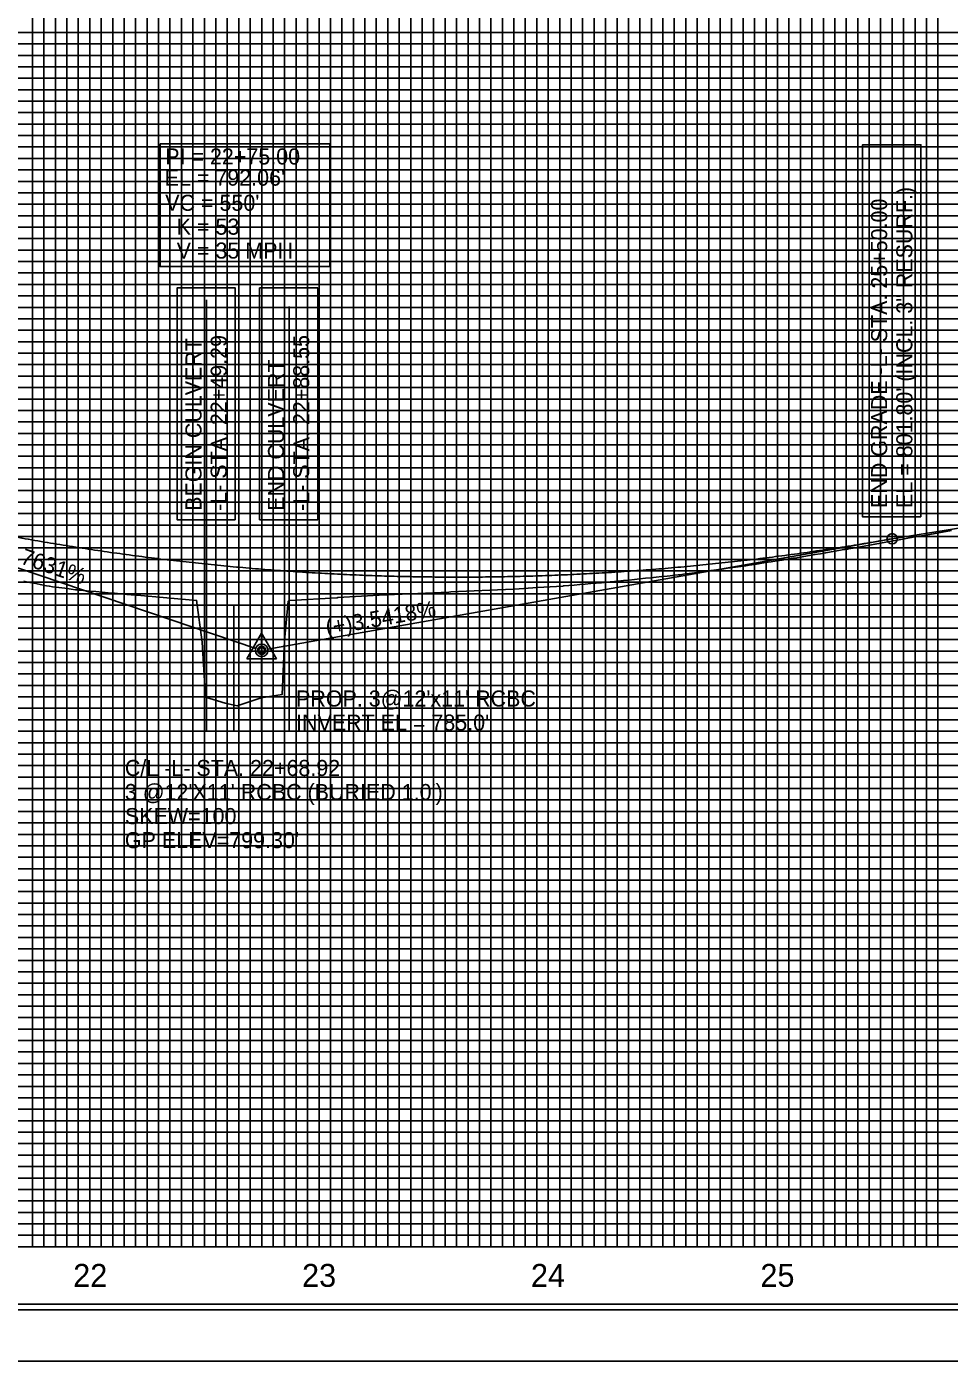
# Model space of a CAD drawing. Extents: x 573566 to 575250, y -53414 to -52314.
# Drawn here: x 574256 to 574658, y -53414 to -52832 of the extents above; entities that cross this region are included whole.
import ezdxf

# ---------------------------------------------------------------- set-up
doc = ezdxf.new("R2010")
doc.units = 0
for name, color, linetype in [('Default', 7, 'Continuous'), ('Exist Vertical Profile Ground Line', 7, 'Continuous'), ('Exist Vertical Profile Horizontal Axis Label Major', 7, 'Continuous'), ('Prop Grid Mask', 7, 'Continuous'), ('Prop PFL VPI Symbol CELL', 7, 'Continuous'), ('Prop Roadway Culvert', 7, 'Continuous'), ('Prop Vertical Profile Curve Label', 7, 'Continuous'), ('Prop Vertical Profile Grade', 7, 'Continuous'), ('Prop Vertical Profile Grade Label', 7, 'Continuous'), ('Prop VPI Label', 7, 'Continuous'), ('Sheet Cutting Line CELL', 7, 'Continuous'), ('Sheet DOT Grid CELL', 7, 'Continuous'), ('Sheet Layout Profile Border', 7, 'Continuous'), ('Sheet Plot Border Inside CELL', 7, 'Continuous'), ('Sheet Plot Border Outside CELL', 7, 'Continuous'), ('Sheet Profile CELL', 7, 'Continuous'), ('Sheet Profile Grid Major CELL', 7, 'Continuous'), ('Sheet Profile Grid Middle CELL', 7, 'Continuous'), ('Sheet Profile Grid Minor CELL', 7, 'Continuous')]:
    doc.layers.add(name, color=color, linetype=linetype)

msp = doc.modelspace()

# ---------------------------------------------------------------- linework, layer by layer
at = {"layer": 'Default'}
for p, q in [((574370.23, -53084.05), (574334.23, -53084.05)), ((574358.23, -53084.05), (574358.23, -53139.05))]:
    msp.add_line(p, q, dxfattribs=at)
at = {"layer": 'Exist Vertical Profile Ground Line'}
for points in [[(574606.77, -53060.75), (574609.15, -53060.34), (574611.54, -53059.93), (574612.73, -53059.73), (574613.92, -53059.53), (574614.33, -53059.46), (574616.31, -53059.11), (574618.69, -53058.68), (574621.08, -53058.25), (574623.47, -53057.82), (574625.85, -53057.39), (574628.24, -53056.96), (574630.62, -53056.53), (574633.01, -53056.11), (574635.39, -53055.68), (574636.4, -53055.5), (574637.78, -53055.27), (574638.68, -53055.12), (574640.16, -53054.85), (574642.55, -53054.41), (574644.93, -53053.98), (574647.32, -53053.55), (574649.7, -53053.12), (574652.09, -53052.68), (574654.47, -53052.25), (574656.86, -53051.82), (574659.25, -53051.39)], [(574261.72, -53075), (574264.42, -53075.53), (574265.72, -53075.79), (574267.12, -53075.97), (574269.81, -53076.32), (574272.51, -53076.67), (574275.21, -53077.02), (574277.12, -53077.27), (574277.9, -53077.38), (574278.31, -53077.44), (574280.6, -53077.65), (574283.3, -53077.89), (574285.99, -53078.13), (574288.69, -53078.38), (574291.39, -53078.61), (574294.08, -53078.85), (574296.78, -53079.09), (574299.48, -53079.32), (574303.21, -53079.65), (574304.04, -53079.7), (574329.89, -53081.96), (574329.92, -53081.9), (574332.41, -53100.16), (574333.76, -53124.19), (574342.33, -53126.75), (574347.68, -53128.02), (574354.21, -53125.83), (574358.02, -53124.4), (574367.22, -53123.06), (574368.19, -53099.62), (574369.93, -53082.34), (574370.37, -53081.94), (574391.18, -53080.77), (574391.57, -53080.75), (574412.16, -53079.59), (574412.93, -53079.55), (574439.93, -53078.3), (574440.86, -53078.25), (574467.94, -53077.07), (574468.66, -53077.03), (574478.69, -53076.38), (574489.68, -53075.67), (574489.89, -53075.65), (574490.3, -53075.62), (574492.27, -53075.45), (574494.66, -53075.24), (574497.04, -53075.04), (574499.43, -53074.83), (574501.82, -53074.62), (574504.2, -53074.42), (574506.59, -53074.21), (574508.97, -53074), (574510.26, -53073.89), (574511.36, -53073.8), (574512.18, -53073.74), (574513.74, -53073.57), (574516.13, -53073.32), (574518.51, -53073.07), (574520.9, -53072.82), (574523.28, -53072.57), (574525.67, -53072.31), (574528.05, -53072.06), (574530.44, -53071.81), (574532.82, -53071.56), (574535.21, -53071.31), (574537.59, -53071.05), (574538.1, -53071), (574539.98, -53070.81), (574540.84, -53070.73), (574542.37, -53070.52), (574544.75, -53070.2), (574547.14, -53069.88), (574549.52, -53069.56), (574551.91, -53069.23), (574554.29, -53068.91), (574556.68, -53068.59), (574559.06, -53068.26), (574561.45, -53067.94), (574563.83, -53067.61), (574566.22, -53067.29), (574568.6, -53066.96), (574568.61, -53066.96), (574569.46, -53066.84), (574570.99, -53066.6), (574573.37, -53066.23), (574575.76, -53065.85), (574578.14, -53065.47), (574580.53, -53065.09), (574582.92, -53064.71), (574582.99, -53064.7), (574585.3, -53064.34), (574587.69, -53063.96), (574590.07, -53063.58), (574591.81, -53063.31), (574592.46, -53063.2), (574594.84, -53062.79), (574597.23, -53062.38), (574599.61, -53061.98), (574602, -53061.57), (574604.38, -53061.16), (574606.77, -53060.75)], [(574254.52, -53073.59), (574256.33, -53073.95), (574259.03, -53074.48), (574261.72, -53075)]]:
    msp.add_lwpolyline(points, dxfattribs=at)
at = {"layer": 'Prop Grid Mask'}
for points in [[(574314.01, -52882.62), (574388.03, -52882.62), (574388.03, -52936.22), (574314.01, -52936.22)], [(574645.87, -53045.49), (574620.46, -53045.49), (574620.46, -52883.04), (574645.87, -52883.04)], [(574346.79, -53046.76), (574321.38, -53046.76), (574321.38, -52945.55), (574346.79, -52945.55)], [(574382.79, -53046.76), (574357.38, -53046.76), (574357.38, -52945.55), (574382.79, -52945.55)]]:
    msp.add_lwpolyline(points, close=True, dxfattribs=at)
at = {"layer": 'Prop PFL VPI Symbol CELL'}
for p, q in [((574358.3, -53096.27), (574351.85, -53107.47)), ((574358.3, -53096.27), (574364.8, -53107.47)), ((574351.85, -53107.47), (574364.8, -53107.47))]:
    msp.add_line(p, q, dxfattribs=at)
for radius in [1.75, 1.2]:
    msp.add_circle((574358.31, -53103.75), radius, dxfattribs=at)
at = {"layer": 'Prop Roadway Culvert'}
for p, q in [((574334.23, -53079.05), (574370.23, -53079.05)), ((574334.23, -53139.05), (574334.23, -53079.05)), ((574370.23, -53139.05), (574370.23, -53079.05)), ((574334.23, -53084.05), (574370.23, -53084.05)), ((574346.23, -53139.05), (574346.23, -53084.05)), ((574358.23, -53139.05), (574358.23, -53084.05)), ((574334.23, -53139.05), (574370.23, -53139.05))]:
    msp.add_line(p, q, dxfattribs=at)
at = {"layer": 'Prop Vertical Profile Curve Label'}
msp.add_circle((574633.31, -53055.05), 2.25, dxfattribs=at)
at = {"layer": 'Prop Vertical Profile Grade'}
msp.add_line((574633.31, -53055.05), (574683.31, -53047.03), dxfattribs=at)
msp.add_spline([(574083.31, -53010.76), (574094.31, -53014.42), (574105.31, -53017.97), (574116.31, -53021.41), (574127.31, -53024.73), (574138.31, -53027.94), (574149.31, -53031.03), (574160.31, -53034.02), (574171.31, -53036.89), (574182.31, -53039.64), (574193.31, -53042.29), (574204.31, -53044.82), (574215.31, -53047.23), (574226.31, -53049.53), (574237.31, -53051.72), (574248.31, -53053.8), (574259.31, -53055.76), (574270.31, -53057.61), (574281.31, -53059.35), (574292.31, -53060.97), (574303.31, -53062.48), (574314.31, -53063.88), (574325.31, -53065.16), (574336.31, -53066.33), (574347.31, -53067.38), (574358.31, -53068.33), (574369.31, -53069.16), (574380.31, -53069.87), (574391.31, -53070.47), (574402.31, -53070.96), (574413.31, -53071.34), (574424.31, -53071.6), (574435.31, -53071.75), (574446.31, -53071.79), (574457.31, -53071.71), (574468.31, -53071.52), (574479.31, -53071.21), (574490.31, -53070.79), (574501.31, -53070.26), (574512.31, -53069.62), (574523.31, -53068.86), (574534.31, -53067.99), (574545.31, -53067.01), (574556.31, -53065.91), (574567.31, -53064.7), (574578.31, -53063.37), (574589.31, -53061.93), (574600.31, -53060.38), (574611.31, -53058.72), (574622.31, -53056.94), (574633.31, -53055.05)], degree=3, dxfattribs=at)
at = {"layer": 'Prop VPI Label'}
for p, q in [((574633.31, -53055.05), (574633.31, -52884.81)), ((574334.23, -53079.05), (574334.23, -52950.82)), ((574370.23, -53079.05), (574370.23, -52953.7)), ((574083.31, -53010.76), (574355.7, -53102.87)), ((574633.31, -53055.05), (574361.01, -53103.27))]:
    msp.add_line(p, q, dxfattribs=at)
msp.add_circle((574358.31, -53103.75), 2.75, dxfattribs=at)
at = {"layer": 'Sheet Cutting Line CELL'}
msp.add_line((573566.31, -53414.05), (575250.31, -53414.05), dxfattribs=at)
at = {"layer": 'Sheet DOT Grid CELL'}
for p, q in [((574283.31, -52339.05), (574283.31, -53364.05)), ((574333.31, -52339.05), (574333.31, -53364.05)), ((574383.31, -52339.05), (574383.31, -53364.05)), ((574433.31, -52339.05), (574433.31, -53364.05)), ((574483.31, -52339.05), (574483.31, -53364.05)), ((574533.31, -52339.05), (574533.31, -53364.05)), ((574583.31, -52339.05), (574583.31, -53364.05)), ((574633.31, -52339.05), (574633.31, -53364.05)), ((573733.31, -52864.05), (575233.31, -52864.05)), ((573733.31, -52914.05), (575233.31, -52914.05)), ((573733.31, -52964.05), (575233.31, -52964.05)), ((573733.31, -53014.05), (575233.31, -53014.05)), ((573733.31, -53064.05), (575233.31, -53064.05)), ((573733.31, -53114.05), (575233.31, -53114.05)), ((573733.31, -53164.05), (575233.31, -53164.05)), ((573733.31, -53214.05), (575233.31, -53214.05)), ((573733.31, -53264.05), (575233.31, -53264.05)), ((573733.31, -53314.05), (575233.31, -53314.05))]:
    msp.add_line(p, q, dxfattribs=at)
at = {"layer": 'Sheet Layout Profile Border'}
msp.add_lwpolyline([(573783.31, -52339.05), (573783.31, -53364.05), (575183.31, -53364.05), (575183.31, -52476.6), (575033.26, -52476.6), (575033.26, -52339.05)], close=True, dxfattribs=at)
at = {"layer": 'Sheet Plot Border Inside CELL'}
msp.add_lwpolyline([(575245.81, -52336.5), (573579.31, -52336.5), (573579.31, -53391.6), (575245.81, -53391.6)], close=True, dxfattribs=at)
at = {"layer": 'Sheet Plot Border Outside CELL'}
msp.add_lwpolyline([(575250.31, -52314.05), (573566.31, -52314.05), (573566.31, -53414.05), (575250.31, -53414.05)], close=True, dxfattribs=at)
at = {"layer": 'Sheet Profile CELL'}
msp.add_line((575233.31, -53364.05), (573733.31, -53364.05), dxfattribs=at)
msp.add_lwpolyline([(575233.31, -52339.05), (573733.31, -52339.05), (573733.31, -53389.05), (575233.31, -53389.05)], close=True, dxfattribs=at)
at = {"layer": 'Sheet Profile Grid Major CELL'}
for points in [[(574283.31, -52339.05), (574283.31, -53364.05), (574333.31, -53364.05), (574333.31, -52339.05)], [(574383.31, -52339.05), (574383.31, -53364.05), (574433.31, -53364.05), (574433.31, -52339.05)], [(574483.31, -52339.05), (574483.31, -53364.05), (574533.31, -53364.05), (574533.31, -52339.05)], [(574583.31, -52339.05), (574583.31, -53364.05), (574633.31, -53364.05), (574633.31, -52339.05)], [(575233.31, -52914.05), (573733.31, -52914.05), (573733.31, -52864.05), (575233.31, -52864.05)], [(575233.31, -53014.05), (573733.31, -53014.05), (573733.31, -52964.05), (575233.31, -52964.05)], [(575233.31, -53114.05), (573733.31, -53114.05), (573733.31, -53064.05), (575233.31, -53064.05)], [(575233.31, -53214.05), (573733.31, -53214.05), (573733.31, -53164.05), (575233.31, -53164.05)], [(575233.31, -53314.05), (573733.31, -53314.05), (573733.31, -53264.05), (575233.31, -53264.05)]]:
    msp.add_lwpolyline(points, dxfattribs=at)
at = {"layer": 'Sheet Profile Grid Middle CELL'}
for points in [[(574258.31, -52339.05), (574258.31, -53364.05), (574308.31, -53364.05), (574308.31, -52339.05)], [(574358.31, -52339.05), (574358.31, -53364.05), (574408.31, -53364.05), (574408.31, -52339.05)], [(574458.31, -52339.05), (574458.31, -53364.05), (574508.31, -53364.05), (574508.31, -52339.05)], [(574558.31, -52339.05), (574558.31, -53364.05), (574608.31, -53364.05), (574608.31, -52339.05)], [(575233.31, -52839.05), (573733.31, -52839.05), (573733.31, -52889.05), (575233.31, -52889.05)], [(575233.31, -52939.05), (573733.31, -52939.05), (573733.31, -52989.05), (575233.31, -52989.05)], [(575233.31, -53039.05), (573733.31, -53039.05), (573733.31, -53089.05), (575233.31, -53089.05)], [(575233.31, -53139.05), (573733.31, -53139.05), (573733.31, -53189.05), (575233.31, -53189.05)], [(575233.31, -53239.05), (573733.31, -53239.05), (573733.31, -53289.05), (575233.31, -53289.05)], [(575233.31, -53339.05), (573733.31, -53339.05)]]:
    msp.add_lwpolyline(points, dxfattribs=at)
at = {"layer": 'Sheet Profile Grid Minor CELL'}
for points in [[(574263.31, -52339.05), (574263.31, -53364.05)], [(574268.31, -52339.05), (574268.31, -53364.05), (574273.31, -53364.05), (574273.31, -52339.05), (574278.31, -52339.05), (574278.31, -53364.05), (574288.31, -53364.05), (574288.31, -52339.05), (574293.31, -52339.05), (574293.31, -53364.05), (574298.31, -53364.05), (574298.31, -52339.05), (574303.31, -52339.05), (574303.31, -53364.05)], [(574313.31, -53364.05), (574313.31, -52339.05)], [(574318.31, -52339.05), (574318.31, -53364.05), (574323.31, -53364.05), (574323.31, -52339.05)], [(574328.31, -52339.05), (574328.31, -53364.05), (574338.31, -53364.05), (574338.31, -52339.05)], [(574343.31, -52339.05), (574343.31, -53364.05), (574343.31, -53364.05), (574348.31, -53364.05), (574348.31, -52339.05)], [(574353.31, -52339.05), (574353.31, -53364.05), (574363.31, -53364.05), (574363.31, -52339.05)], [(574368.31, -52339.05), (574368.31, -53364.05), (574373.31, -53364.05), (574373.31, -52339.05)], [(574378.31, -52339.05), (574378.31, -53364.05), (574388.31, -53364.05), (574388.31, -52339.05)], [(574393.31, -52339.05), (574393.31, -53364.05), (574398.31, -53364.05), (574398.31, -52339.05)], [(574403.31, -52339.05), (574403.31, -53364.05), (574413.31, -53364.05), (574413.31, -52339.05)], [(574418.31, -52339.05), (574418.31, -53364.05), (574423.31, -53364.05), (574423.31, -52339.05)], [(574428.31, -52339.05), (574428.31, -53364.05), (574438.31, -53364.05), (574438.31, -52339.05)], [(574443.31, -52339.05), (574443.31, -53364.05), (574448.31, -53364.05), (574448.31, -52339.05)], [(574453.31, -52339.05), (574453.31, -53364.05), (574463.31, -53364.05), (574463.31, -52339.05)], [(574468.31, -52339.05), (574468.31, -53364.05), (574473.31, -53364.05), (574473.31, -52339.05)], [(574478.31, -52339.05), (574478.31, -53364.05), (574488.31, -53364.05), (574488.31, -52339.05)], [(574493.31, -52339.05), (574493.31, -53364.05)], [(574493.31, -53364.05), (574498.31, -53364.05), (574498.31, -52339.65)], [(574503.31, -52339.65), (574503.31, -53364.05), (574513.31, -53364.05), (574513.31, -52339.05)], [(574518.31, -52339.05), (574518.31, -53364.05), (574523.31, -53364.05), (574523.31, -52339.05)], [(574528.31, -52339.05), (574528.31, -53364.05), (574538.31, -53364.05), (574538.31, -52339.05)], [(574543.31, -52339.05), (574543.31, -53364.05), (574548.31, -53364.05), (574548.31, -52339.05)], [(574553.31, -52339.05), (574553.31, -53364.05), (574563.31, -53364.05), (574563.31, -52339.05)], [(574568.31, -52339.05), (574568.31, -53364.05), (574573.31, -53364.05), (574573.31, -52339.05)], [(574578.31, -52339.05), (574578.31, -53364.05), (574588.31, -53364.05), (574588.31, -52339.05)], [(574593.31, -52339.05), (574593.31, -53364.05), (574598.31, -53364.05), (574598.31, -52339.05)], [(574603.31, -52339.05), (574603.31, -53364.05), (574613.31, -53364.05), (574613.31, -52339.05)], [(574618.31, -52339.05), (574618.31, -53364.05), (574623.31, -53364.05), (574623.31, -52339.05)], [(574628.31, -52339.05), (574628.31, -53364.05), (574638.31, -53364.05), (574638.31, -52339.05)], [(574643.31, -52339.05), (574643.31, -53364.05), (574648.31, -53364.05), (574648.31, -52339.05)], [(574653.31, -52339.05), (574653.31, -53364.05), (574663.31, -53364.05)], [(575183.31, -52834.05), (573783.31, -52834.05), (573783.31, -52844.05), (575183.31, -52844.05)], [(575183.31, -52849.05), (573783.31, -52849.05), (573783.31, -52854.05), (575183.31, -52854.05)], [(575183.31, -52859.05), (573783.31, -52859.05)], [(573783.31, -52869.05), (575183.31, -52869.05)], [(575183.31, -52874.05), (573783.31, -52874.05), (573783.31, -52879.05), (575183.31, -52879.05)], [(575183.31, -52884.05), (573783.31, -52884.05), (573783.31, -52894.05), (575183.31, -52894.05)], [(575183.31, -52899.05), (573783.31, -52899.05), (573783.31, -52904.05), (575183.31, -52904.05)], [(575183.31, -52909.05), (573783.31, -52909.05), (573783.31, -52919.05), (575183.31, -52919.05)], [(575183.31, -52924.05), (573783.31, -52924.05), (573783.31, -52929.05), (575183.31, -52929.05)], [(575183.31, -52934.05), (573783.31, -52934.05), (573783.31, -52944.05), (575183.31, -52944.05)], [(575183.31, -52949.05), (573783.31, -52949.05), (573783.31, -52954.05), (575183.31, -52954.05)], [(575183.31, -52959.05), (573783.31, -52959.05), (573783.31, -52969.05), (575183.31, -52969.05)], [(575183.31, -52974.05), (573783.31, -52974.05), (573783.31, -52979.05), (575183.31, -52979.05)], [(575183.31, -52984.05), (573783.31, -52984.05), (573783.31, -52994.05), (575183.31, -52994.05)], [(575183.31, -52999.05), (573783.31, -52999.05), (573783.31, -53004.05), (575183.31, -53004.05)], [(575183.31, -53009.05), (573783.31, -53009.05), (573783.31, -53019.05), (575183.31, -53019.05)], [(575183.31, -53024.05), (573783.31, -53024.05), (573783.31, -53029.05), (575183.31, -53029.05)], [(575183.31, -53034.05), (573783.31, -53034.05), (573783.31, -53044.05), (575183.31, -53044.05)], [(575183.31, -53049.05), (573783.31, -53049.05), (573783.31, -53054.05), (575183.31, -53054.05)], [(575183.31, -53059.05), (573783.31, -53059.05), (573783.31, -53069.05), (575183.31, -53069.05)], [(575183.31, -53074.05), (573783.31, -53074.05), (573783.31, -53079.05), (575183.31, -53079.05)], [(575183.31, -53084.05), (573783.31, -53084.05), (573783.31, -53094.05), (575183.31, -53094.05)], [(575183.31, -53099.05), (573783.31, -53099.05), (573783.31, -53104.05), (575183.31, -53104.05)], [(575183.31, -53109.05), (573783.31, -53109.05), (573783.31, -53119.05), (575183.31, -53119.05)], [(575183.31, -53124.05), (573783.31, -53124.05), (573783.31, -53129.05), (575183.31, -53129.05)], [(575183.31, -53134.05), (573783.31, -53134.05), (573783.31, -53144.05), (575183.31, -53144.05)], [(575183.31, -53149.05), (573783.31, -53149.05), (573783.31, -53154.05), (575183.31, -53154.05)], [(575183.31, -53159.05), (573783.31, -53159.05)], [(573783.31, -53169.05), (575183.31, -53169.05)], [(575183.31, -53174.05), (573783.31, -53174.05), (573783.31, -53179.05), (575183.31, -53179.05)], [(575183.31, -53184.05), (573783.31, -53184.05)], [(573783.31, -53194.05), (575183.31, -53194.05)], [(575183.31, -53199.05), (573783.31, -53199.05), (573783.31, -53204.05), (575183.31, -53204.05)], [(575183.31, -53209.05), (573783.31, -53209.05), (573783.31, -53219.05), (575183.31, -53219.05)], [(575183.31, -53224.05), (573783.31, -53224.05), (573783.31, -53229.05), (575183.31, -53229.05)], [(575183.31, -53234.05), (573783.31, -53234.05), (573783.31, -53244.05), (575183.31, -53244.05)], [(575183.31, -53249.05), (573783.31, -53249.05), (573783.31, -53254.05), (575183.31, -53254.05)], [(575183.31, -53259.05), (573783.31, -53259.05), (573783.31, -53269.05), (575183.31, -53269.05)], [(575183.31, -53274.05), (573783.31, -53274.05), (573783.31, -53279.05), (575183.31, -53279.05)], [(575183.31, -53284.05), (573783.31, -53284.05), (573783.31, -53294.05), (575183.31, -53294.05)], [(575183.31, -53299.05), (573783.31, -53299.05), (573783.31, -53304.05), (575183.31, -53304.05)], [(575183.31, -53309.05), (573783.31, -53309.05), (573783.31, -53319.05), (575183.31, -53319.05)], [(575183.31, -53324.05), (573783.31, -53324.05), (573783.31, -53329.05), (575183.31, -53329.05)], [(575183.31, -53334.05), (573783.31, -53334.05), (573783.31, -53344.05), (575183.31, -53344.05)], [(575183.31, -53349.05), (573783.31, -53349.05), (573783.31, -53354.05), (575183.31, -53354.05)], [(575183.31, -53359.05), (573783.31, -53359.05)]]:
    msp.add_lwpolyline(points, dxfattribs=at)

# ---------------------------------------------------------------- texts
at = {"layer": 'Exist Vertical Profile Horizontal Axis Label Major'}
for s, p in [('22', (574276.08, -53381.55)), ('23', (574375.92, -53381.55)), ('24', (574475.76, -53381.55)), ('25', (574575.85, -53381.55))]:
    msp.add_text(s, height=10, dxfattribs=at).set_placement(p)
at = {"layer": 'Prop Roadway Culvert'}
for s, p in [("PROP. 3@12'x11' RCBC", (574373.29, -53128.26)), ("INVERT EL = 785.0'", (574373.29, -53138.76)), ('C/L -L- STA. 22+68.92', (574298.63, -53158.58)), ("3 @12'X11' RCBC (BURIED 1.0')", (574298.63, -53169.08)), ('SKEW=100', (574298.63, -53179.58)), ("GP ELEV=799.30'", (574298.63, -53190.08))]:
    msp.add_text(s, height=7, rotation=0.00001, dxfattribs=at).set_placement(p)
at = {"layer": 'Prop Vertical Profile Curve Label'}
for s, p in [("VC = 550'", (574316.23, -52911.91)), ('K = 53', (574321.23, -52922.33)), ('V = 35 MPH', (574321.23, -52932.75))]:
    msp.add_text(s, height=7, dxfattribs=at).set_placement(p)
at = {"layer": 'Prop Vertical Profile Grade Label'}
for s, rotation, p in [('(-)6.7631%', 341.31684, (574236.38, -53060.26)), ('(+)3.5418%', 10.04244, (574386.85, -53097.32))]:
    msp.add_text(s, height=7, rotation=rotation, dxfattribs=at).set_placement(p)
at = {"layer": 'Prop VPI Label'}
for s, p in [('PI = 22+75.00', (574316.23, -52891.67)), ("EL = 792.06'", (574315.98, -52900.93))]:
    msp.add_text(s, height=7, dxfattribs=at).set_placement(p)
for s, p in [('EL = 801.80\' (INCL. 3" RESURF.)', (574642.14, -53041.6)), ('END GRADE -L- STA. 25+50.00 ', (574631.14, -53041.6)), ('-L- STA. 22+49.29', (574343.06, -53042.87)), ('-L- STA. 22+88.55', (574379.06, -53042.87)), ('BEGIN CULVERT', (574332.06, -53042.87)), ('END CULVERT', (574368.06, -53042.87))]:
    msp.add_text(s, height=7, rotation=90, dxfattribs=at).set_placement(p)

doc.saveas('drawing.dxf')
